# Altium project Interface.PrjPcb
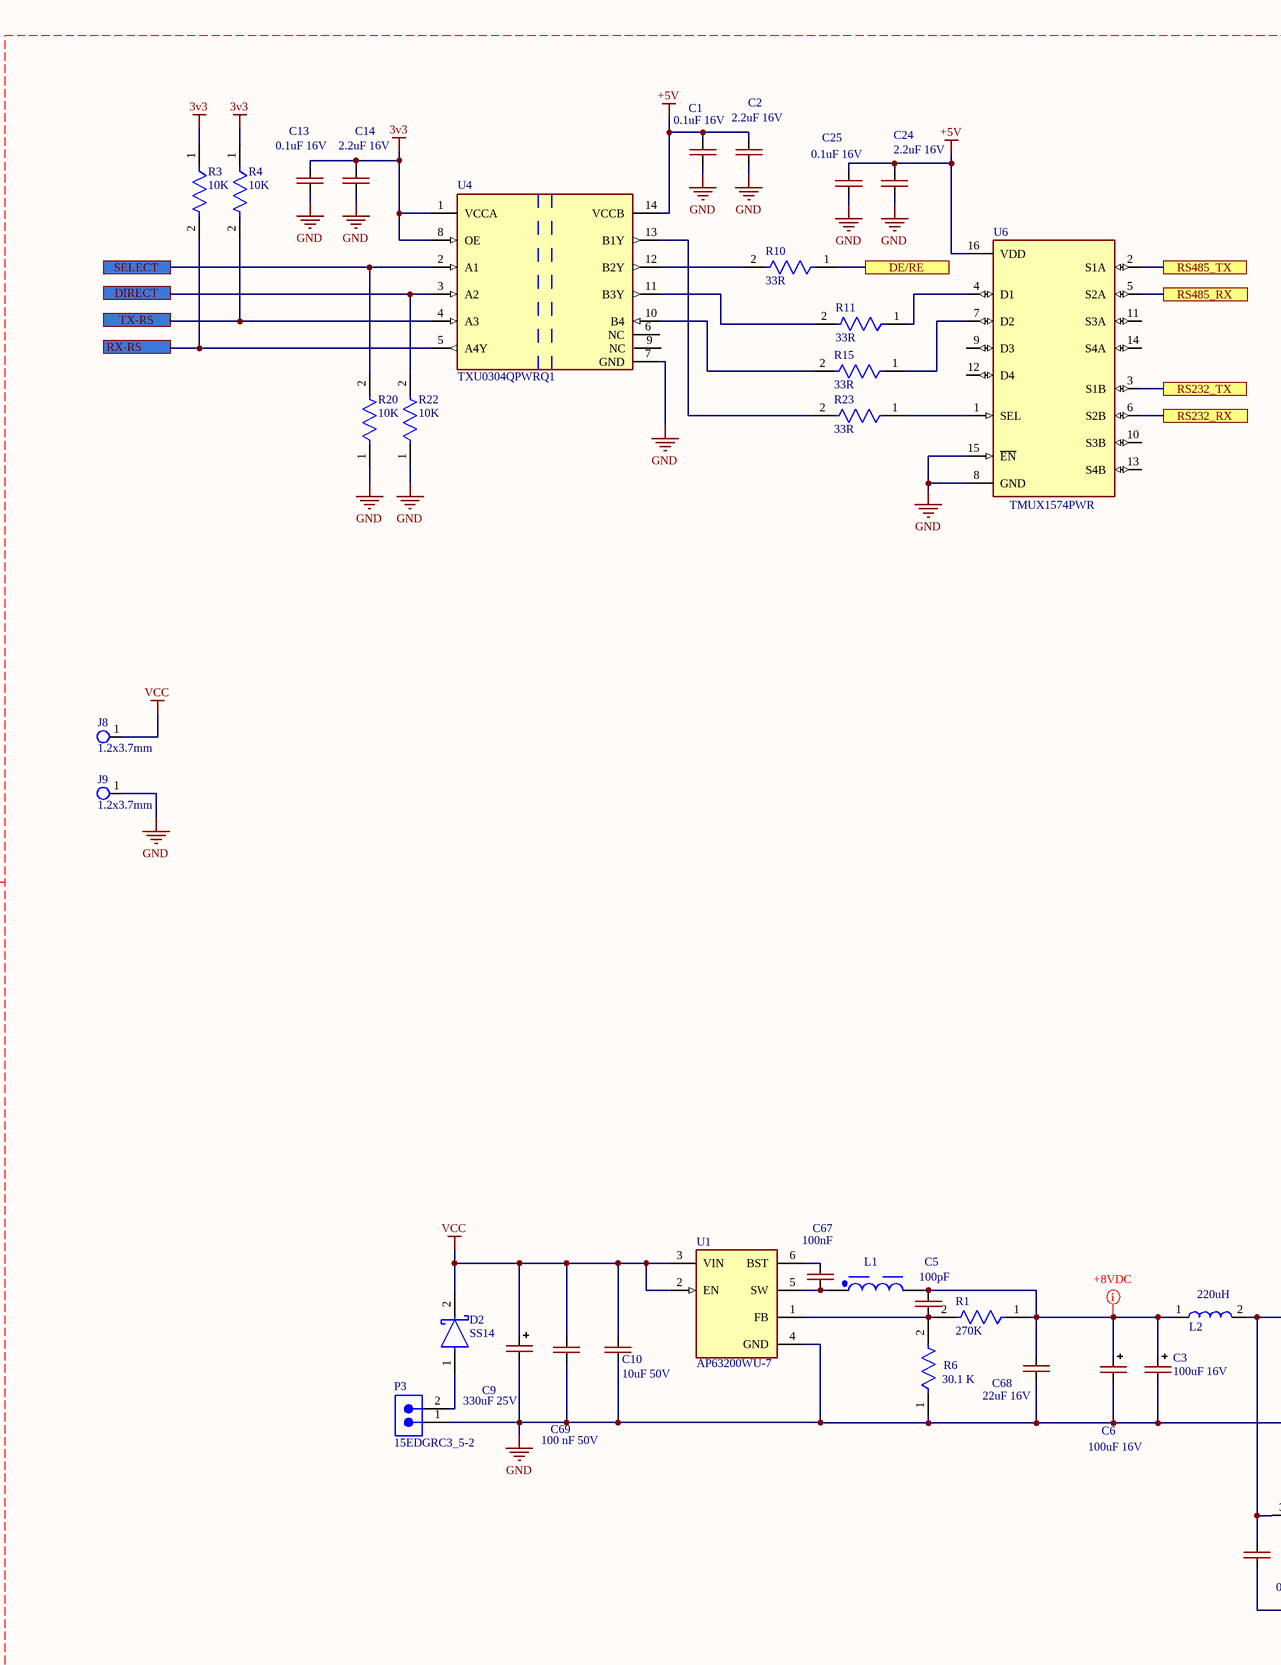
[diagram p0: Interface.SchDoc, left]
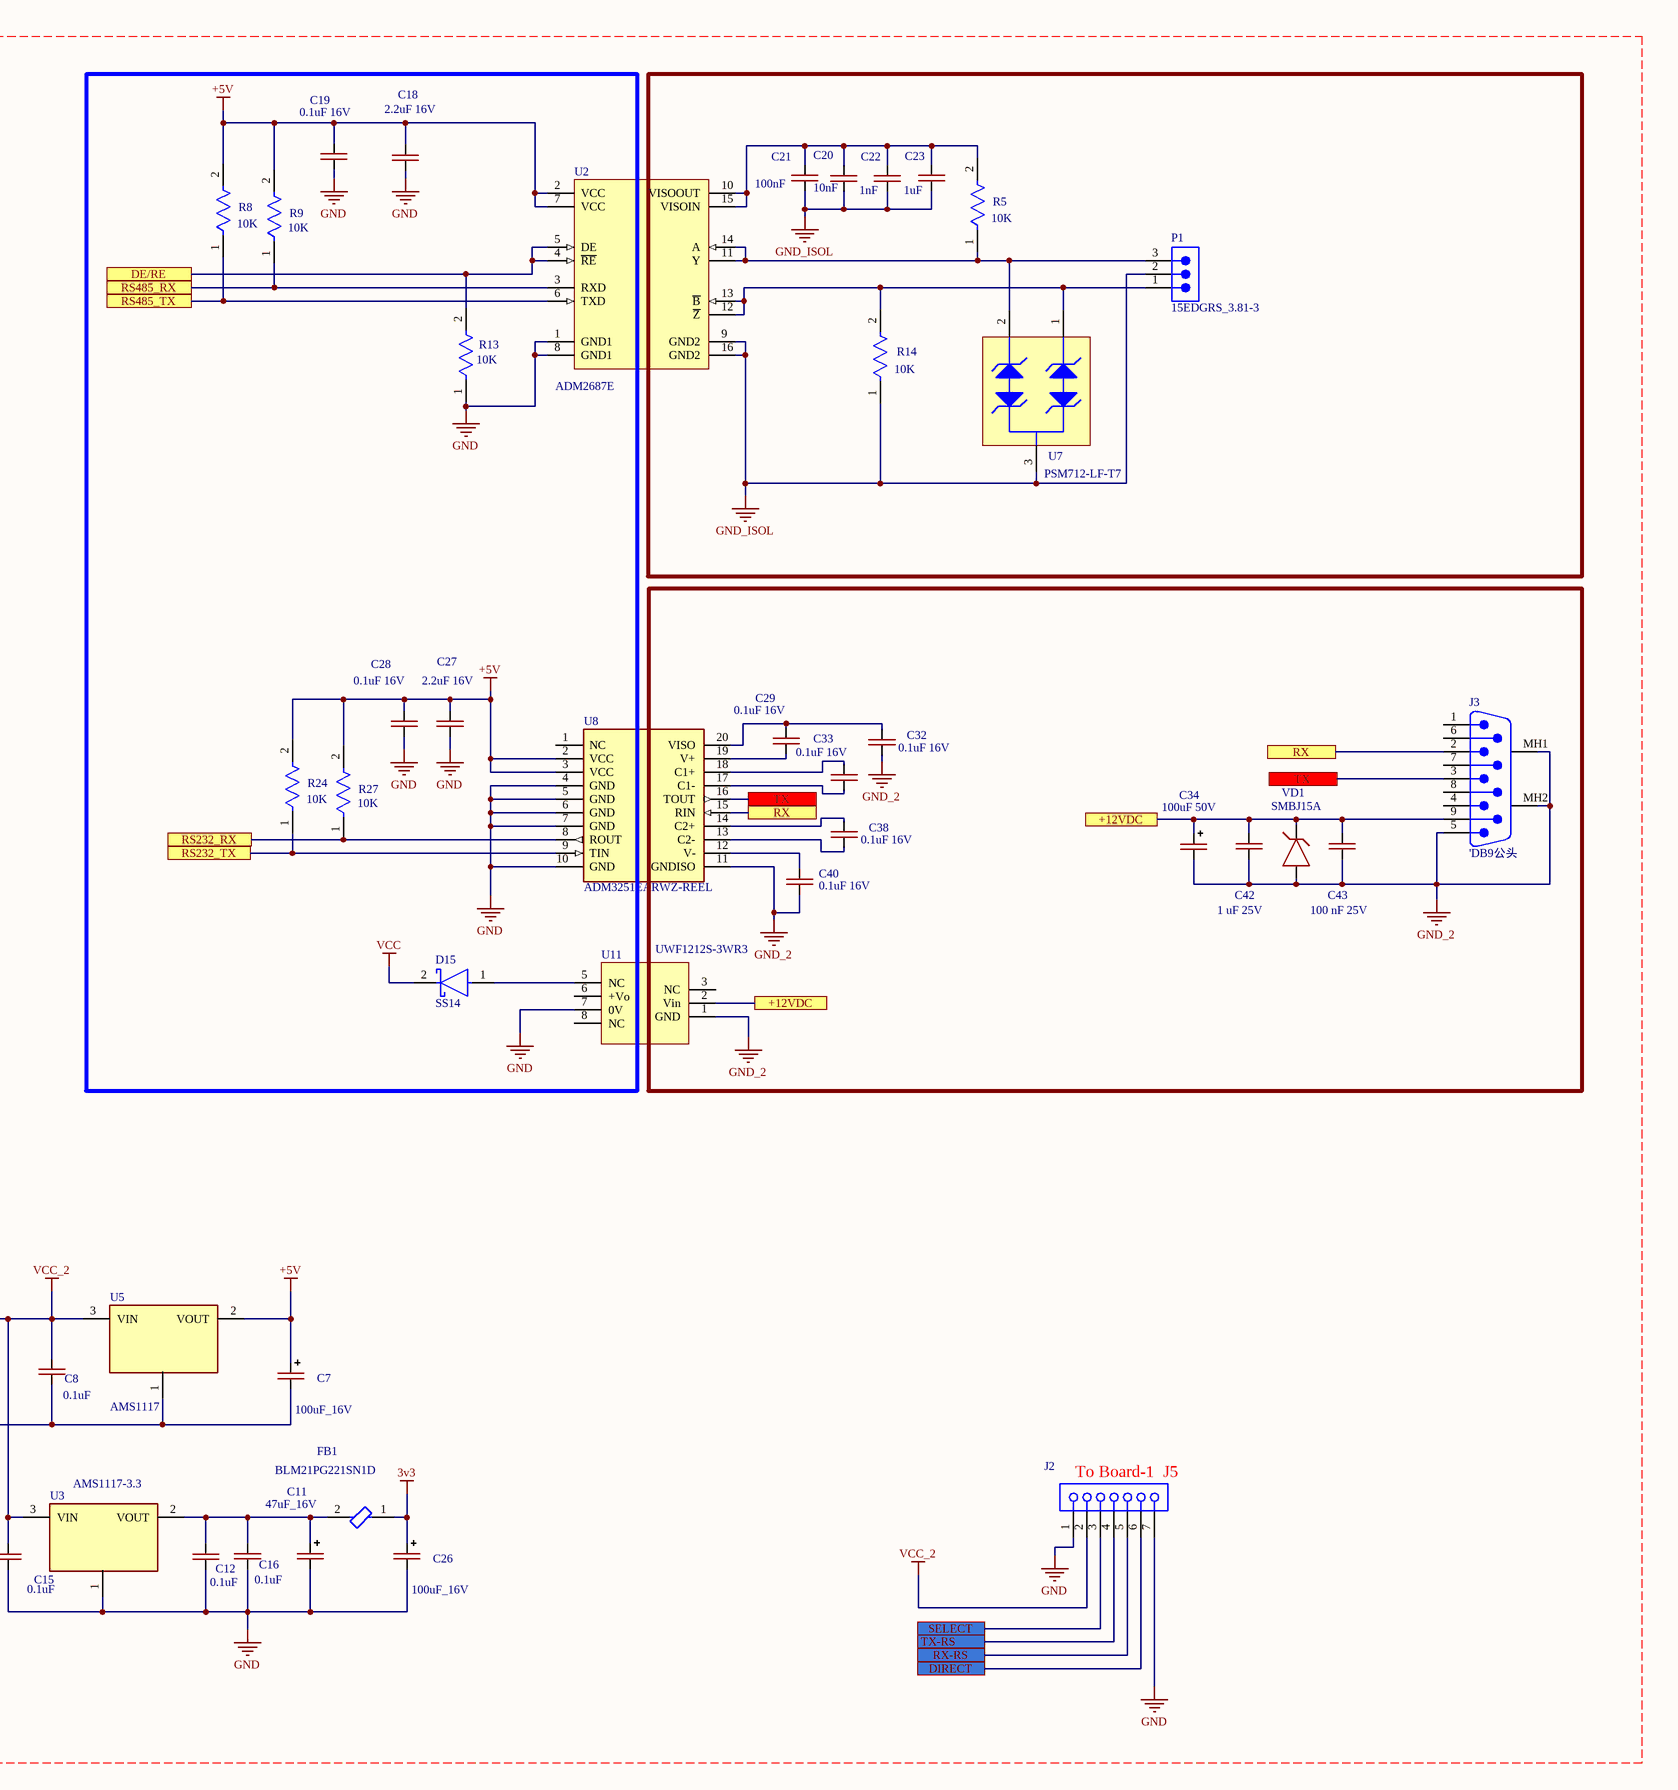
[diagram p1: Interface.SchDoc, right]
1 sheet, 75 parts. Net scope: flat (ports and power ports of the same name join across sheets).
Board file: Interface.PcbDoc

## Sheet Interface.SchDoc
size A1; SheetNumber: 1; SheetTotal: 1; SPICEModelCacheNLVBOJOE: <root> / <DocumentId>NLVBOJOE</DocumentId> / <CacheFrame Number="0"> / <Model Name="5848_744774112_12u" Kind="CKT"> / <Text>******* / .subckt 5848_744774112_12u 1 2 / Rp 1 2 22000 / Cp 1 2 3p / Rs 1 N3 0.065 / L1 N3 2 12u / .ends 5848_744774112_12u</Text> / </Model> / </CacheFrame> / </root>

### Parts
C1  0.1uF 16V  [CAP-0402]
C2  2.2uF 16V  [CAP-0402]
C3  100uF 16V  [CAP_A765EB_KEM-L]
C5  100pF  [CAP-0603]
C6  100uF 16V  [CAP_A765EB_KEM]
C7  100uF_16V  [CAP-TAN-C]
C8  0.1uF  [CAP-0603]
C9  330uF 25V  [CAP_SMD_Size_G]
C10  10uF 50V  [CAP-1206]
C11  47uF_16V  [CAP-TAN-C]
C12  0.1uF  [CAP-0603]
C13  0.1uF 16V  [CAP-0402]
C14  2.2uF 16V  [CAP-0402]
C15  0.1uF  [CAP-0603]
C16  0.1uF  [CAP-0603]
C18  2.2uF 16V  [CAP-0402]
C19  0.1uF 16V  [CAP-0402]
C20  10nF  [CAP-0402]
C21  100nF  [CAP-0402]
C22  1nF  [CAP-0402]
C23  1uF  [CAP-0603]
C24  2.2uF 16V  [CAP-0402]
C25  0.1uF 16V  [CAP-0402]
C26  100uF_16V  [CAP-TAN-C]
C27  2.2uF 16V  [CAP-0402]
C28  0.1uF 16V  [CAP-0402]
C29  0.1uF 16V  [CAP-0603]
C32  0.1uF 16V  [CAP-0603]
C33  0.1uF 16V  [CAP-0603]
C34  100uF 50V  [CAP_SMD_SIZE_D]
C38  0.1uF 16V  [CAP-0603]
C40  0.1uF 16V  [CAP-0603]
C42  1 uF 25V  [CAP-0805]
C43  100 nF 25V  [CAP-0805]
C67  100nF  [CAP-0603]
C68  22uF 16V  [CAP-1206]
C69  100 nF 50V  [CAP-0603]
D2  SS14  [DO-214-AC]
D15  SS14  [DO-214-AC]
FB1  BLM21PG221SN1D  [FP-BLM21-0_2-t0_85-e0_5-IPC_A]
J2  61300711821  [61300711821]  (value not drawn)
J3  'DB9公头  [DB9-1]
J8  1.2x3.7mm  [Pad_conn_1.2x3.7mm]
J9  1.2x3.7mm  [Pad_conn_1.2x3.7mm]
L1  12µH, 2A  [WE-PD2_5848]  (value not drawn)
L2  220uH  [Coil_4.5x4.5_mm]
P1  15EDGRS_3.81-3  [15EDGRC-3.81-3]
P3  15EDGRC3_5-2  [16EDGRC_3.81-2]
R1  270K  [RES-0402]
R3  10K  [RES-0402]
R4  10K  [RES-0402]
R5  10K  [RES-0402]
R6  30.1 K  [RES-0402]
R8  10K  [RES-0402]
R9  10K  [RES-0402]
R10  33R  [RES-0402]
R11  33R  [RES-0402]
R13  10K  [RES-0402]
R14  10K  [RES-0402]
R15  33R  [RES-0402]
R20  10K  [RES-0402]
R22  10K  [RES-0402]
R23  33R  [RES-0402]
R24  10K  [RES-0402]
R27  10K  [RES-0402]
U1  AP63200WU-7  [FP-TSOT26-MFG]
U2  ADM2687E  [RI_16_2_ADI-L]
U3  AMS1117-3.3  [SOT-89]
U4  TXU0304QPWRQ1  [FP-PW0014A-IPC_B]
U5  AMS1117  [SOT-89]
U6  TMUX1574PWR  [TSSOP-16-A]
U7  PSM712-LF-T7  [PRKT-SOT23-3_V]
U8  ADM3251EARWZ-REEL  [FP-RW-20-IPC_B]
U11  UWF1212S-3WR3  [UWF_S-3WR3]
VD1  SMBJ15A  [DO-214AA]

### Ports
+12VDC, DE/RE, DIRECT, RS232_RX, RS232_TX, RS485_RX, RS485_TX, RX, RX-RS, SELECT, TX, TX-RS

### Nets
3v3: C13.1 C14.1 C26.1(+) FB1.1 R3.1 R4.1 U4.1(VCCA) U4.8(OE)
+5V: C1.1 C2.1 C7.1(+) C18.1 C19.1 C24.1 C25.1 C27.1 C28.1 R8.2 R9.2 R24.2 R27.2 U2.2(VCC) U2.7(VCC) U4.14(VCCB) U5.2(VOUT) U6.16(VDD) U8.2(VCC) U8.3(VCC)
GND: C1.2 C2.2 C3.2(-) C6.2(-) C7.2(-) C8.1 C9.2(-) C10.2 C11.2(-) C12.1 C13.2 C14.2 C15.1 C16.1 C18.2 C19.2 C24.2 C25.2 C26.2(-) C27.2 C28.2 C68.2 C69.2 J2.1 J2.7 J9.1 P3.1 R6.1 R13.1 R20.1 R22.1 U1.4(GND) U2.1(GND1) U2.8(GND1) U3.1(Ground) U4.7(GND) U5.1(Ground) U6.8(GND) U6.15(~{EN}) U8.4(GND) U8.5(GND) U8.6(GND) U8.7(GND) U8.10(GND) U11.7(0V)
GND_2: C32.1 C34.2(-) C40.1 C42.2 C43.2 J3.5 J3.MH1 J3.MH2 U8.11(GNDISO) U11.1(GND) VD1.2(A)
GND_ISOL: C20.2 C21.2 C22.2 C23.2 P1.2 R14.1 U2.9(GND2) U2.16(GND2) U7.3
VCC: C9.1(+) C10.1 C69.1 D2.2(C) D15.2(C) J8.1 U1.2(EN) U1.3(VIN)
VCC_2: C8.2 C15.2 J2.2 L2.2 U3.3(VIN) U5.3(VIN)
NetC3_1: C3.1(+) C5.1 C6.1(+) C68.1 L1.2 L2.1 R1.1
NetC5_2: C5.2 R1.2 R6.2 U1.1(FB)
NetC11_1: C11.1(+) C12.2 C16.2 FB1.2 U3.2(VOUT)
NetC20_1: C20.1 C21.1 C22.1 C23.1 R5.2 U2.10(VISOOUT) U2.15(VISOIN)
NetC29_1: C29.1 U8.19(V+)
NetC29_2: C29.2 C32.2 U8.20(VISO)
NetC33_1: C33.1 U8.17(C1-)
NetC33_2: C33.2 U8.18(C1+)
NetC34_1: C34.1(+) C42.1 C43.1 J3.9 U11.2(Vin) VD1.1(C) ; port +12VDC
NetC38_1: C38.1 U8.13(C2-)
NetC38_2: C38.2 U8.14(C2+)
NetC40_2: C40.2 U8.12(V-)
NetC67_1: C67.1 U1.6(BST)
NetC67_2: C67.2 L1.1 U1.5(SW)
NetD2_1: D2.1(A) P3.2
NetD15_1: D15.1(A) U11.5(NC)
NetJ2_3: J2.3 R20.2 U4.2(A1) ; port SELECT
NetJ2_4: J2.4 R4.2 U4.4(A3) ; port TX-RS
NetJ2_5: J2.5 R3.2 U4.5(A4Y) ; port RX-RS
NetJ2_6: J2.6 R22.2 U4.3(A2) ; port DIRECT
NetJ3_2: J3.2 U8.15(RIN) ; port RX
NetJ3_3: J3.3 U8.16(TOUT) ; port TX
NetP1_1: P1.1 R14.2 U2.12(~{Z}) U2.13(~{B}) U7.1
NetP1_3: P1.3 R5.1 U2.11(Y) U2.14(A) U7.2
NetR8_1: R8.1 U2.6(TXD) U6.2(S1A) ; port RS485_TX
NetR9_1: R9.1 U2.3(RXD) U6.5(S2A) ; port RS485_RX
NetR10_1: R10.1 R13.2 U2.4(~{RE}) U2.5(DE) ; port DE/RE
NetR10_2: R10.2 U4.12(B2Y)
NetR11_1: R11.1 U6.4(D1)
NetR11_2: R11.2 U4.11(B3Y)
NetR15_1: R15.1 U6.7(D2)
NetR15_2: R15.2 U4.10(B4)
NetR23_1: R23.1 U6.1(SEL)
NetR23_2: R23.2 U4.13(B1Y)
NetR24_1: R24.1 U6.3(S1B) U8.9(TIN) ; port RS232_TX
NetR27_1: R27.1 U6.6(S2B) U8.8(ROUT) ; port RS232_RX

Not connected (* = marked no-connect by the designer): J3 1 4 6 7 8; U4 6(NC) 9(NC); U6 9(D3) 10(S3B) 11(S3A) 12(D4) 13(S4B) 14(S4A); U8 1(NC); U11 3(NC) 6(+Vo) 8(NC)

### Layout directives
mark named +8VDC: NetC3_1
CompClassName: Interface: 3v3, +5V, GND, GND_2, GND_ISOL, VCC, VCC_2

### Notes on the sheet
- (near J2) To Board-1  J5

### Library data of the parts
C1 C13 C19 C25 C28 = CAP-NON-POLAR: 0.1uF 16V X7R / GRM155R71C104KA88D
C2 C14 C18 C24 C27 = CAP-NON-POLAR: 2.2uF 16V X5R GRM155R61C225KE11D
C3 C6 = CAP_POL_SMD: KEMET A765EB107M1CLAE025 / 100uF 16V 25mΩ 125mA@120Hz ±20% SMD,D6.3xL6mm Aluminum
C5 = CAP-NON-POLAR: 100pF 50V  C0G   Murata GRM1885C1H101JA01D
C7 C9 C26 = CAP_POL_SMD
C8 C12 C15 C16 C20-C23 C29 C32 C33 C38 C40 = CAP-NON-POLAR
C10 = CAP-NON-POLAR: 10uF 50V X7R  Yageo  CC1206KKX7R9BB106
C11 = CAP-POLAR
C34 = CAP_POL_SMD: 100uF 50V  JVJ50V100M6x8
C42 = CAP-NON-POLAR: 1 uF 25V X7R
C43 = CAP-NON-POLAR: 100 nF 25V X7R
C67 = CAP-NON-POLAR: 100nF  50V  X7R  Murata GRM188R71H104KA93D
C68 = CAP-NON-POLAR: 22uF 16V   X7R   Murata GRM31CZ71C226ME15L
C69 = CAP-NON-POLAR: 100 nF 50V  X7R  GCM188R71H104KA57J
FB1 = BLM21PG221SN1D: Chip Ferrite Bead, 0805, 220Ω @ 100MHz, 0.045Ω, 25%, 2A
J2 = 61300711821: WR-PHD Socket Header, THT, Vertical, pitch 2.54mm, 1 Row, 7P; Manufacturer: Wurth Elektronik; Contact Resistance: 20mΩ; Rated Current: 3A; Working Voltage: 250V; Withstanding Voltage: 500V
J3 = DB9: D-DMR009PM-D002  Ckmtw / 9P/弯插/公
J8 J9 = Klema_15_A
L1 = 744774112: WE-PD2 SMT Power Inductor, size 5848, 12µH, 2A, 0.11Ω; Manufacturer: Wurth Elektronik; Case/Size Code: 5848; DC Resistance: 0.082Ω; Saturation Current: 1.94A; Self Resonant Frequency: 24MHz
L2 = Coil
R1 R3-R5 R8-R11 R13-R15 R20 R22-R24 R27 = RES-CONST
R6 = RES-CONST: 30,1 K, 1%
U1 = AP63200WU-7: AP63200WU-7  IC REG BUCK ADJUSTABLE 2A TSOT26
U3 = AMS1117
U4 = TXU0304QPWRQ1: Translation - Voltage Levels Automotive four chan nel unidirectional
U7 = CMP-2000-07553-1: TVS Array - Asymmetrical Data Line Protector, 600 W, 7.5 V, -55 to 150 degC, 3-Pin SOT23, RoHS, Tape and Reel; Manufacturer: Protek Devices; Min Breakdown Voltage: 7.5V; Direction: Bidirectional; Capacitance: 75pF; Current: 20uA; Power Dissipation: 600W; Working Voltage: 7V; Voltage: 12V; Case\/Package: SOT-23; Clamping Voltage: 17V; Element Configuration: Dual
U8 = ADM3251EARWZ-REEL: DGTL ISO 2.5KV 2CH RS232 20SOIC
U11 = UWF_S-3WR3
VD1 = ESD_Unidirect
